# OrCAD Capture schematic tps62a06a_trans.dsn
size D; title: TPS62A06A, High-Efficiency, Synchronous, Buck Converter; rev: 1.0; note: Datasheet: SLUSET0A     EVM: SLUUCP5; note: Synchronous Step Down Converter
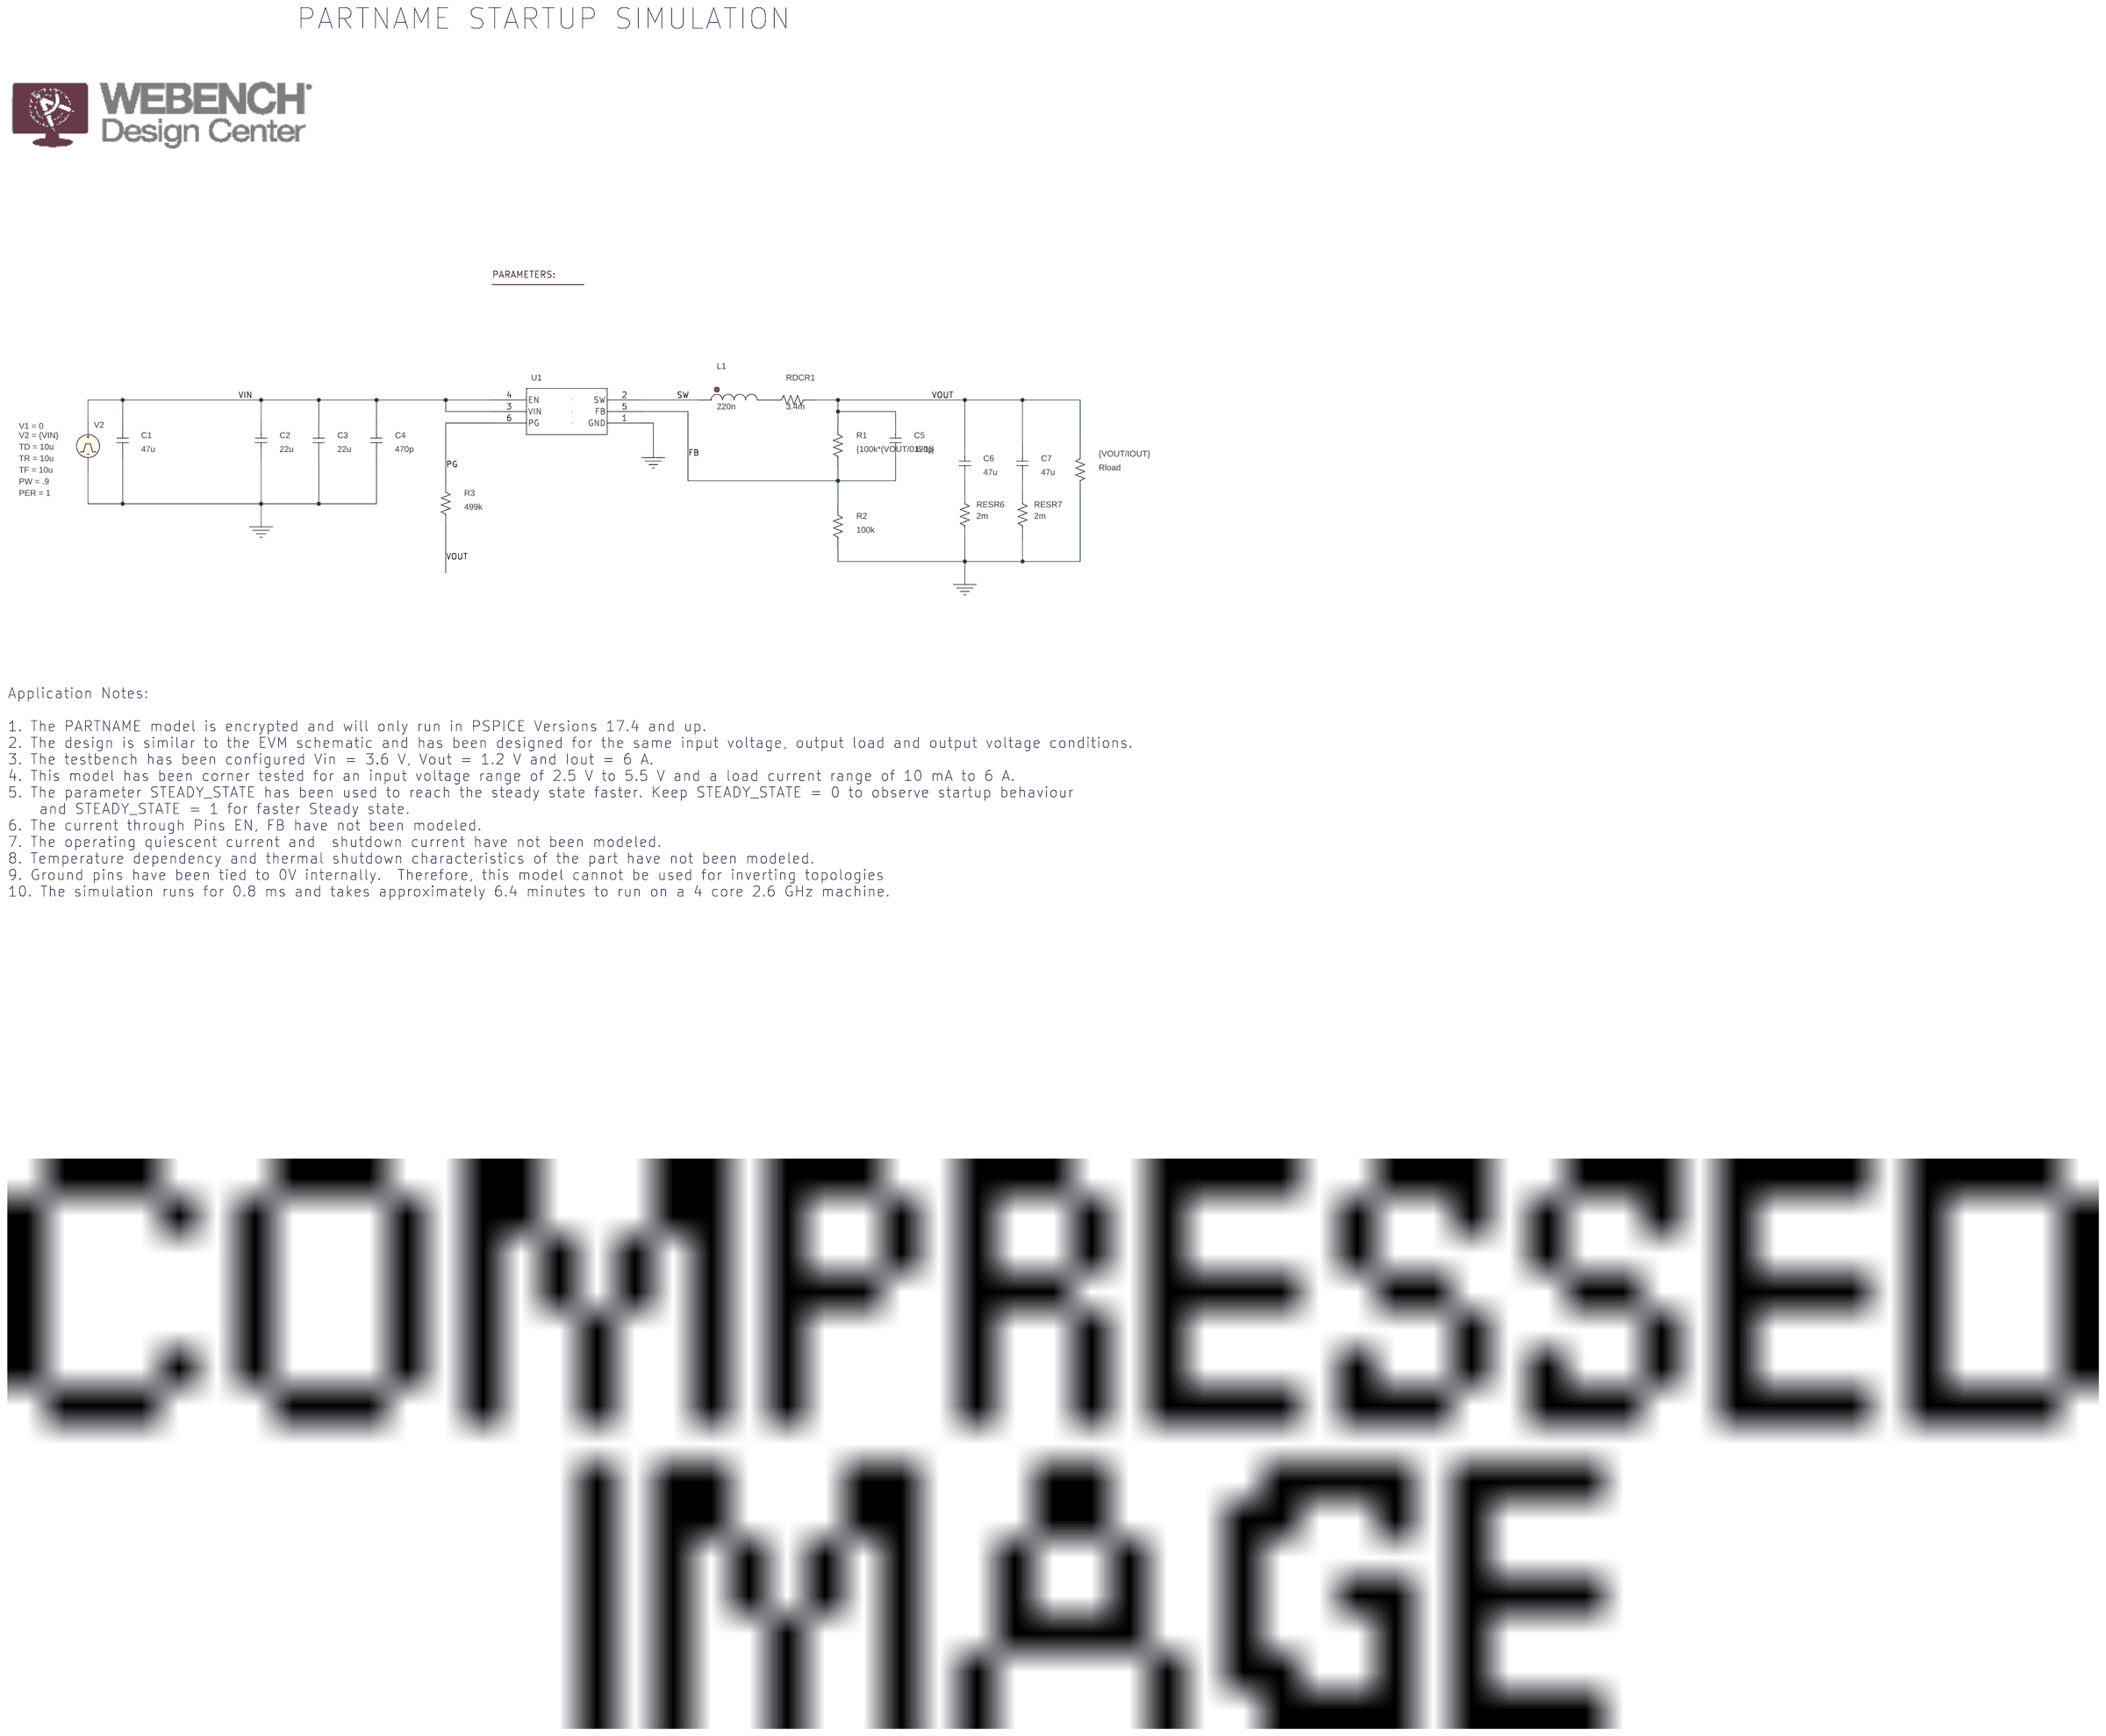
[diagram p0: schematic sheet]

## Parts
1  PARAM
C1  47u  [cap196]
C2  22u  [cap196]
C3  22u  [cap196]
C4  470p  [cap196]
C5  120p  [cap196]
C6  47u  [cap196]
C7  47u  [cap196]
L1  220n  [DISC/.350x.175/LS.200x.100/.034]
R1  {100k*(VOUT/0.6-1)}  [AX/RC05]
R2  100k  [AX/RC05]
R3  499k  [AX/RC05]
RDCR1  3.4m  [AX/RC05]
RESR6  2m  [AX/RC05]
RESR7  2m  [AX/RC05]
Rload  {VOUT/IOUT}  [AX/RC05]
U1  Value  [DRL0006A-MFG]
V2  VPULSE

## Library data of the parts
1 = PARAM: IOUT: 6; SS: 0; VIN: 3.6; VOUT: 1.2
C1-C7 = C
L1 = L
R1-R3 RDCR1 RESR6 RESR7 Rload = R
U1 = TPS62A06ADRL_TRANS
V2 = VPULSE: PER: 1; PW: .9; TD: 10u; TF: 10u; TR: 10u; V1: 0; V2: {VIN}

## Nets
VIN: C1.2 C2.2 C3.2 C4.2 U1.3(VIN) U1.4(EN) V2.1(+)
0: C1.1 C2.1 C3.1 C4.1 R2.1 RESR6.1 RESR7.1 Rload.2 U1.1(GND) V2.2(-)
FB: C5.1 R1.1 R2.2 U1.5(FB)
PG: R3.2 U1.6(PG)
SW: L1.1 U1.2(SW)
VOUT: C5.2 C6.2 C7.2 R1.2 R3.1 RDCR1.2 Rload.1
N16775073: C6.1 RESR6.2
N16775079: C7.1 RESR7.2
N16776039: L1.2 RDCR1.1

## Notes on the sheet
- PARTNAME STARTUP SIMULATION
- Application Notes:
  1. The PARTNAME model is encrypted and will only run in PSPICE Versions 17.4 and up.
  2. The design is similar to the EVM schematic and has been designed for the same input voltage, output load and output voltage conditions.
  3. The testbench has been configured Vin = 3.6 V, Vout = 1.2 V and Iout = 6 A.
  4. This model has been corner tested for an input voltage range of 2.5 V to 5.5 V and a load current range of 10 mA to 6 A.
  5. The parameter STEADY_STATE has been used to reach the steady state faster. Keep STEADY_STATE = 0 to observe startup behaviour
      and STEADY_STATE = 1 for faster Steady state.
  6. The current through Pins EN, FB have not been modeled.
  7. The operating quiescent current and  shutdown current have not been modeled.
  8. Temperature dependency and thermal shutdown characteristics of the part have not been modeled.
  9. Ground pins have been tied to 0V internally.  Therefore, this model cannot be used for inverting topologies
  10. The simulation runs for 0.8 ms and takes approximately 6.4 minutes to run on a 4 core 2.6 GHz machine.
